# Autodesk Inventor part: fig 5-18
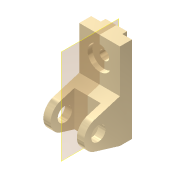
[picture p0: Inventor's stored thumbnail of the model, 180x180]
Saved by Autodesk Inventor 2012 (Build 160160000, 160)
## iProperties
Shininess: 65.0
Angle Display Precision: 2
Document Length Units: 11269
Document Angle Units: 11279
Document Time Units: 11290
Document Mass Units: 11283
Document Length Units Precision: 3
Document Angle Units Precision: 2
Compacted: False
Created: 2001-11
Part Number: fig 5-18
Document SubType Name: Modeling
Designer: Renu Muthoo
Density: 1 g/cm^3
Material: Default
Density: 0.0
Volumn: 0.0
Area: 0.0
PropertySet Name: Model Information
Control State: 0
Master: False
Checked Out: False
Author: Renu Muthoo
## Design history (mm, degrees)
node "Sketch1"
sketch "Sketch2"
  geometry: L1 (33.257, 104.664)-(33.257, -75.336); L2 (33.257, -75.336)-(8.257, -75.336); L3 (8.257, -75.336)-(-45.451, -59.045); L4 (-45.451, -1.628)-(8.257, 14.664); L5 (8.257, 14.664)-(8.257, 104.664); L6 (8.257, 104.664)-(33.257, 104.664); C1 r 15 at (-36.743, -30.336); A1 r 30 centre (-36.743, -30.336) between (-45.451, -1.628) and (-45.451, -59.045)
  constraints: 12 end point, 2 centre point, 2 equal length, 2 parallel, 2 point on circle, 2 tangent, 1 coincident, 1 perpendicular, 1 vertical
  dimensions: "d0" = 180 distance of L1.start L1.end; "d1" = 30 radius of A1; "d2" = 25 distance of L5.end L1.start; "d3" = 45 distance from line of L2 A1.centre; "d4" = 70 distance from line of L1 A1.centre; "d5" = 30 diameter of C1
extrude "Extrusion1" new body sketch "Sketch2" distance "d6" = 85; taper "d7" = 0 deg
workplane "Work Plane1"
sketch "Sketch3"
  geometry: L1 (15, 62.364)-(70, 62.364); L2 (70, 62.364)-(70, -52.386); L3 (70, -52.386)-(15, -52.386); L4 (15, -52.386)-(15, 62.364); L5 (0, -45)-(0, -28.708) reference
  constraints: 8 end point, 2 parallel, 1 horizontal, 1 perpendicular
  dimensions: "d8" = 55 distance of L1.start L1.end; "d9" = 15 distance between parallel lines of L5 L4
extrude "Extrusion2" cut sketch "Sketch3" distance "d10" = 50; taper "d11" = 0 deg
sketch "Sketch4"
  geometry: L1 (0, 25)-(85, 25) reference; L2 (0, 0)-(0, 25) reference; L3 (20, 25)-(65, 25); L4 (65, 25)-(65, 35); L5 (65, 35)-(20, 35); L6 (20, 35)-(20, 25)
  constraints: 8 end point, 2 parallel, 1 horizontal, 1 perpendicular, 1 point on line
  dimensions: "d12" = 45 distance of L4.end L5.end; "d13" = 10 distance of L3.end L4.end; "d14" = 20 distance between parallel lines of L2 L6
extrude "Extrusion3" join sketch "Sketch4" stored distance "d15" = 50; taper "d16" = 0 deg
sketch "Sketch5"
  geometry: L1 (85, 0)-(85, 90) reference; L2 (0, 90)-(85, 90) reference; 1 further point
  dimensions: "d17" = 42 distance from line of L2 point (42.5, 48); "d18" = 42.5 distance from line of L1 point (42.5, 48)
hole "Hole1" sketch "Sketch5" at (42.5, 48) diameter "d19" = 20; stored, may be unused: countersink angle "d23" = 82 deg, drill point angle "d25" = 118 deg; dims "d20" = 6, "d21" = 50, "d22" = 10, "d24" = 8
workplane "Work Plane9"
body "Solid1"
